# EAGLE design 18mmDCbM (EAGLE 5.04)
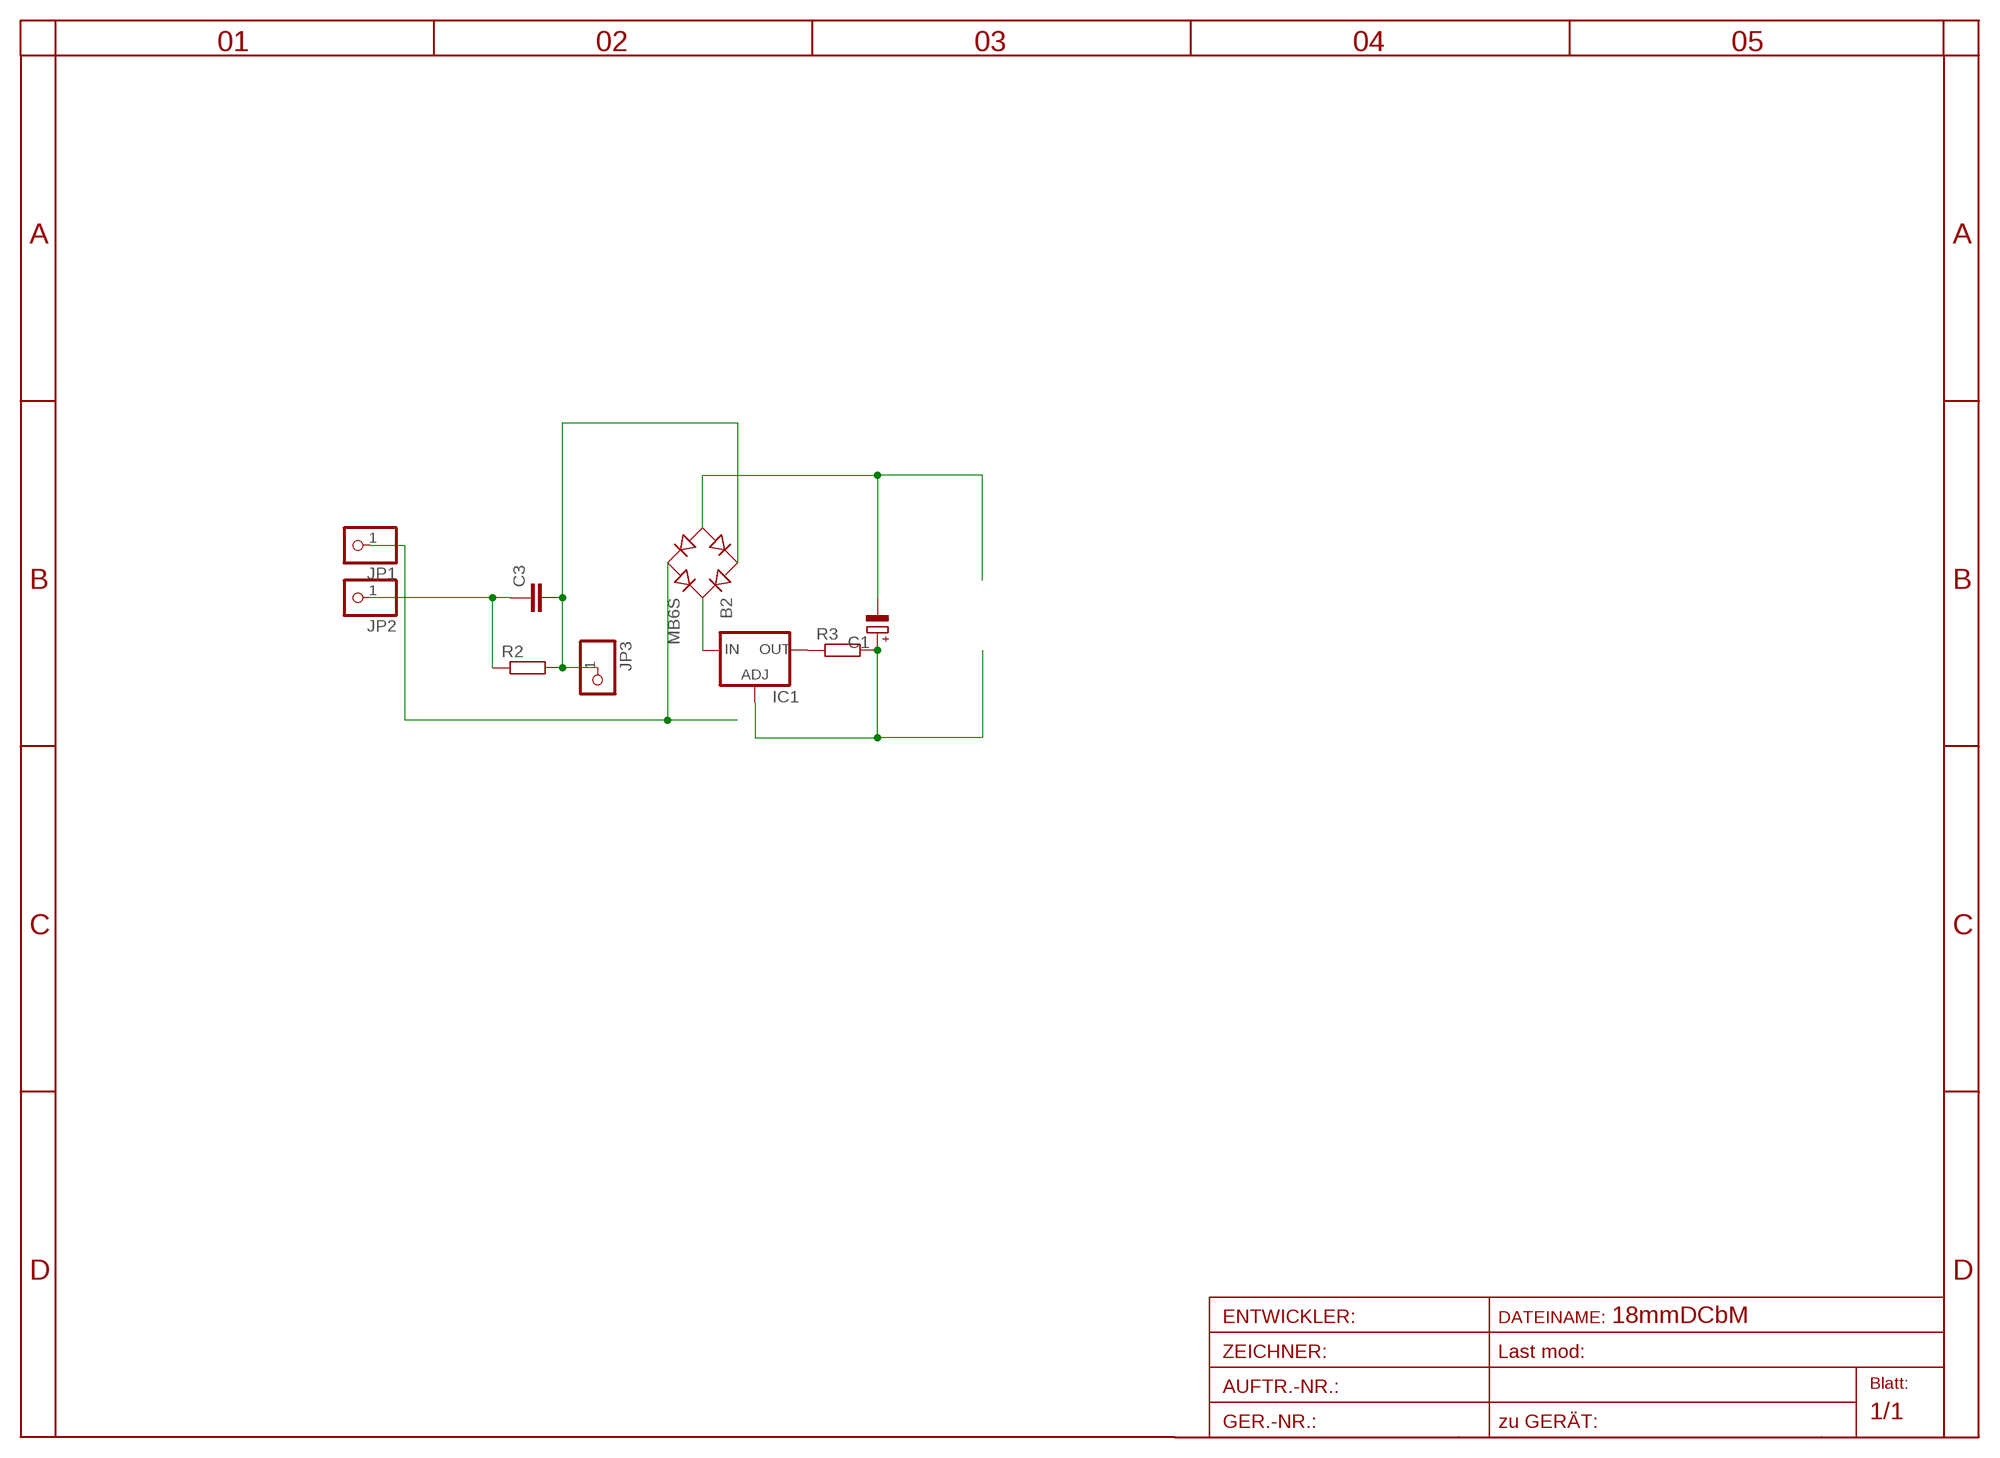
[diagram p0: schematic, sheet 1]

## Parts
B2  MB6S  [SOIC-4]
C1  CPOL-EUE5-13  [E5-13]
C3  C-EU150-054X183  [C150-054X183]
IC1  LM317LZ  [317L]
JP1  PINHD-1X1  [1X01]
JP2  PINHD-1X1  [1X01]
JP3  PINHD-1X1  [1X01]
R2  R-EU_R1206  [R1206]
R3  R-EU_0204/2V  [0204V]

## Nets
AC1: B2.~1(AC1) C3.2 JP3.1 R2.2
AC2: B2.~2(AC2) JP1.1
AC+: C3.1 JP2.1 R2.1
N$2: B2.+ IC1.3(IN)
N$5: IC1.2(OUT) R3.1
PLUS: C1.+ IC1.1(ADJ) R3.2
V-: B2.- C1.-

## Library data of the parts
B2 = rectifier:MB*S: Bridge Rectifier Source: http://www.fairchildsemi.com/ds/MB/MB6S.pdf
C1 = rcl-2:CPOL-EU: POLARIZED CAPACITOR, European symbol
C3 = rcl:C-EU: CAPACITOR, European symbol
IC1 = v-reg-3:LM317L: Adjustable Voltage Regulator, 1.2V to 37V, 100mA
JP1-JP3 = pinhead:PINHD-1X1: PIN HEADER
R2 R3 = rcl:R-EU_: RESISTOR, European symbol

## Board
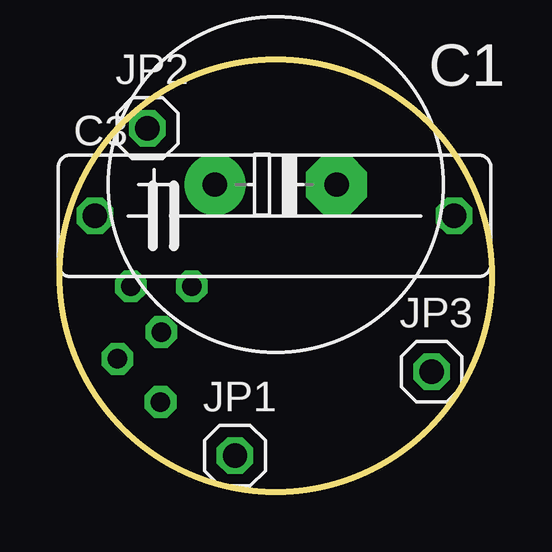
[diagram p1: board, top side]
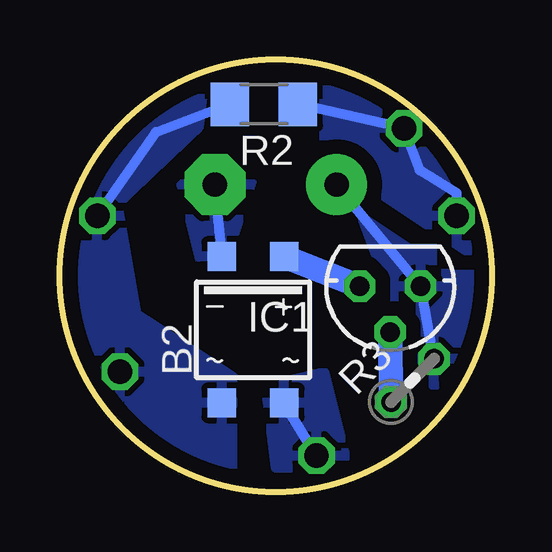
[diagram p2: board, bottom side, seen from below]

Size 18 x 18 mm. Coordinates in mm from the lower left corner, seen from the top.
Outline: circle at 9,9 radius 9
Copper layers (1*16): Top 0.035mm / dielectric 1.5mm / Bottom 0.035mm
Design rules "default *": minimum track width 10mil, minimum drill 24mil, track to track 8mil, track to pad 8mil, pad to pad 8mil, via to via 8mil, smd to smd 8mil, copper to edge 4mil, drill to drill 8mil, minimum pad ring 10mil, minimum via ring 8mil, stop-mask expansion 4mil, vias tented up to drill 0mil, thermal gap 10mil

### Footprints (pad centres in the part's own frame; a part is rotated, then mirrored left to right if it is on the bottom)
SOIC-4 = smd 1.2 x 1.2: + 1.3,3.05; - -1.3,3.05; ~1 -1.3,-3.05; ~2 1.3,-3.05
E5-13 = drill 1.016 pad 2.54 round: + -2.54,0 | drill 1.016 pad 2.54 octagon: - 2.54,0
C150-054X183 = drill 1.016 octagon: 1 -7.493,0; 2 7.493,0
317L = drill 0.813 octagon: 1 -1.27,0; 2 0,1.905; 3 1.27,0
1X01 = drill 1.016 octagon: 1 0,0
R1206 = smd 1.6 x 1.803: 1 -1.422,0; 2 1.422,0
0204V = drill 0.813 octagon: 1 -1.27,0; 2 1.27,0

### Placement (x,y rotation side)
B2  9.95,6.75 0 bottom
C1  9,12.8 0 top
C3  8.95,11.5 0 top
IC1  4.22,8.56 180 bottom
JP1  7.3,1.5 0 top
JP2  3.65,15.15 0 top
JP3  15.5,5 0 top
R2  9.5,16.15 180 bottom
R3  3.3,4.64 45 bottom

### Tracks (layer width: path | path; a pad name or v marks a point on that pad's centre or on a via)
AC1
  Bottom 0.406: R2.2 14,15 C3.2
  pour Bottom (isolate 0.61): 12,17 13.4,17 17,13.4 17.8,7.6 15.2,2.4 12.2,0.8 10.8,0.6 10.8,4.8 14.8,7.4 15.6,12 12.2,15.2
AC2
  Bottom 0.406: JP1.1 B2.~2
  pour Bottom (isolate 0.61): 9.4,4.4 7,5 6,1 9,1
AC+
  Bottom 0.406: C3.1 1.46,12.46 3,13.4 JP2.1 R2.1
  pour Bottom (isolate 0.61, rank 2): 7,18 7,14 1,10 0,11 2,15
N$2
  Bottom 1.016: IC1.3 B2.+
N$5
  Bottom 1.016: R3.1 IC1.2
PLUS
  Bottom 0.406: R3.2 IC1.1 C1.+
  pour Bottom (isolate 0.61, rank 3): 6,13 0,9 2,4 3,5
V-
  Bottom 0.406: B2.- C1.-
  pour Bottom (isolate 0.61, rank 2): 11,10 10,13 13,13 12,9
